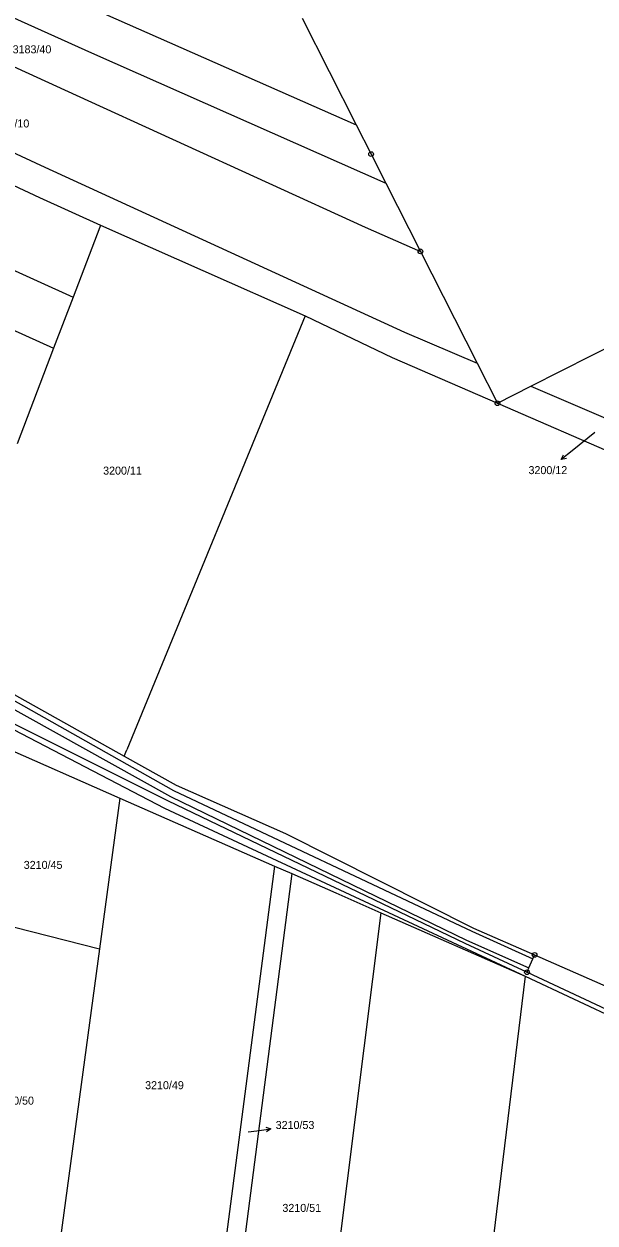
# Model space of a CAD drawing. Extents: x -593183 to -588034, y -1130415 to -1124994.
# Drawn here: x -592330.3 to -592209.1, y -1127958 to -1127703.4 of the extents above; entities that cross this region are included whole.
import ezdxf

# ---------------------------------------------------------------- set-up
doc = ezdxf.new("R2010")
doc.units = 0
for name, color, linetype in [('Vrstva 1', 7, 'Continuous'), ('Vrstva 16', 7, 'Continuous'), ('Vrstva 18', 7, 'Continuous'), ('Vrstva 24', 7, 'Continuous'), ('Vrstva 25', 7, 'Continuous'), ('Vrstva 4', 7, 'Continuous')]:
    doc.layers.add(name, color=color, linetype=linetype)

msp = doc.modelspace()

# ---------------------------------------------------------------- linework, layer by layer
at = {"layer": 'Vrstva 1'}
for p, q in [((-592413.37, -1127665.67), (-592315.98, -1127709.55)), ((-592369.42, -1127695.5), (-592319.21, -1127718.51)), ((-592313.24, -1127701.26), (-592259.77, -1127724.81)), ((-592271.25, -1127702.16), (-592259.77, -1127724.81)), ((-592315.98, -1127709.55), (-592253.49, -1127737.21)), ((-592371.6, -1127712.58), (-592325.84, -1127733.78)), ((-592373.2, -1127718.72), (-592327.02, -1127740.24)), ((-592319.21, -1127718.51), (-592257.85, -1127746.53)), ((-592259.77, -1127724.81), (-592256.62, -1127731.03)), ((-592256.62, -1127731.03), (-592253.49, -1127737.21)), ((-592325.84, -1127733.78), (-592249.53, -1127768.8)), ((-592253.49, -1127737.21), (-592246.16, -1127751.67)), ((-592327.02, -1127740.24), (-592314.04, -1127746.13)), ((-592314.19, -1127746.53), (-592319.85, -1127761.37)), ((-592314.04, -1127746.13), (-592314.19, -1127746.53)), ((-592314.04, -1127746.13), (-592270.63, -1127765.36)), ((-592257.85, -1127746.53), (-592246.16, -1127751.67)), ((-592246.16, -1127751.67), (-592234.12, -1127775.42)), ((-592336.06, -1127754.07), (-592319.85, -1127761.37)), ((-592319.85, -1127761.37), (-592324, -1127772.24)), ((-592339.64, -1127765.19), (-592324, -1127772.24)), ((-592270.63, -1127765.36), (-592308.47, -1127857.54)), ((-592270.63, -1127765.36), (-592252.14, -1127774.24)), ((-592249.53, -1127768.8), (-592234.12, -1127775.42)), ((-592222.71, -1127780.32), (-592203.33, -1127770.51)), ((-592324, -1127772.24), (-592331.75, -1127792.55)), ((-592252.14, -1127774.24), (-592229.81, -1127783.92)), ((-592234.12, -1127775.42), (-592229.81, -1127783.92)), ((-592229.81, -1127783.92), (-592222.71, -1127780.32)), ((-592222.71, -1127780.32), (-592193.62, -1127792.82)), ((-592229.81, -1127783.92), (-592197.03, -1127798.14)), ((-592340.15, -1127841.43), (-592309.01, -1127858.86)), ((-592344.39, -1127846.05), (-592299.69, -1127868.38)), ((-592336.34, -1127856.19), (-592309.98, -1127867.78)), ((-592309.01, -1127858.86), (-592308.47, -1127857.54)), ((-592309.01, -1127858.86), (-592297.99, -1127865.03)), ((-592297.99, -1127865.03), (-592274.79, -1127875.26)), ((-592309.98, -1127867.78), (-592314.29, -1127899.78)), ((-592309.98, -1127867.78), (-592277.12, -1127882.21)), ((-592299.69, -1127868.38), (-592236.73, -1127898.59)), ((-592274.79, -1127875.26), (-592234.91, -1127895.4)), ((-592277.12, -1127882.21), (-592290.68, -1127986.51)), ((-592277.12, -1127882.21), (-592273.46, -1127883.82)), ((-592273.46, -1127883.82), (-592287.07, -1127989.22)), ((-592273.46, -1127883.82), (-592264.12, -1127887.92)), ((-592264.12, -1127887.92), (-592254.55, -1127892.12)), ((-592342.78, -1127892.52), (-592314.29, -1127899.78)), ((-592254.55, -1127892.12), (-592271.16, -1128024.32)), ((-592254.55, -1127892.12), (-592223.89, -1127905.59)), ((-592234.91, -1127895.4), (-592221.92, -1127901.09)), ((-592314.29, -1127899.78), (-592324.47, -1127975.33)), ((-592236.73, -1127898.59), (-592223.53, -1127904.77)), ((-592223.11, -1127903.82), (-592222.26, -1127901.88)), ((-592222.26, -1127901.88), (-592221.92, -1127901.09)), ((-592221.92, -1127901.09), (-592193.32, -1127913.62)), ((-592223.53, -1127904.77), (-592223.11, -1127903.82)), ((-592223.53, -1127904.77), (-592195.18, -1127918.03)), ((-592223.89, -1127905.59), (-592238.76, -1128026.7))]:
    msp.add_line(p, q, dxfattribs=at)
at = {"layer": 'Vrstva 16'}
for p, q in [((-592209.1, -1127790.13), (-592213.91, -1127794.01)), ((-592282.73, -1127938.65), (-592280.86, -1127938.41))]:
    msp.add_line(p, q, dxfattribs=at)
at = {"layer": 'Vrstva 24'}
for centre, radius in [((-592256.62, -1127731.03), 0.5), ((-592256.62, -1127731.03), 0.0327), ((-592246.16, -1127751.67), 0.5), ((-592246.16, -1127751.67), 0.0327), ((-592229.81, -1127783.92), 0.5), ((-592229.81, -1127783.92), 0.0327), ((-592221.92, -1127901.09), 0.5), ((-592221.92, -1127901.09), 0.0327), ((-592223.53, -1127904.77), 0.5), ((-592223.53, -1127904.77), 0.0327)]:
    msp.add_circle(centre, radius, dxfattribs=at)
at = {"layer": 'Vrstva 25'}
for p, q in [((-592213.91, -1127794.01), (-592216.25, -1127795.89)), ((-592280.86, -1127938.41), (-592277.88, -1127938.04))]:
    msp.add_line(p, q, dxfattribs=at)
for points in [[(-592215.15, -1127795.65), (-592216.25, -1127795.89), (-592215.78, -1127794.88)], [(-592278.94, -1127937.66), (-592277.88, -1127938.04), (-592278.81, -1127938.66)]]:
    msp.add_lwpolyline(points, dxfattribs=at)
at = {"layer": 'Vrstva 4'}
for p, q in [((-592337.54, -1127846.06), (-592299.23, -1127867.47)), ((-592336.51, -1127844.77), (-592298.57, -1127866.18)), ((-592339.36, -1127849.65), (-592300.46, -1127869.9)), ((-592298.57, -1127866.18), (-592235.26, -1127896.01)), ((-592299.23, -1127867.47), (-592236.34, -1127897.91)), ((-592300.46, -1127869.9), (-592223.89, -1127905.59)), ((-592235.26, -1127896.01), (-592222.26, -1127901.88)), ((-592236.34, -1127897.91), (-592223.11, -1127903.82)), ((-592223.89, -1127905.59), (-592195.57, -1127918.96))]:
    msp.add_line(p, q, dxfattribs=at)

# ---------------------------------------------------------------- texts
at = {"layer": 'Vrstva 16'}
for s, p in [('3200/12', (-592223.21, -1127798.98)), ('3210/53', (-592276.88, -1127938.04))]:
    msp.add_text(s, height=1.7, dxfattribs=at).set_placement(p)
at = {"layer": 'Vrstva 18'}
for s, height, p in [('3183/40', 1.7, (-592332.71, -1127709.62)), ('3200/10', 1.7, (-592337.39, -1127725.37)), ('3200/11', 1.7, (-592313.5, -1127799.08)), ('3210/45', 1.7, (-592330.35, -1127882.81)), ('3210/49', 1.7, (-592304.59, -1127929.59)), ('3210/50', 1.7, (-592336.4, -1127932.87)), ('3210/53', 0.1, (-592282.73, -1127938.65)), ('3210/51', 1.7, (-592275.45, -1127955.65))]:
    msp.add_text(s, height=height, dxfattribs=at).set_placement(p)

doc.saveas('drawing.dxf')
